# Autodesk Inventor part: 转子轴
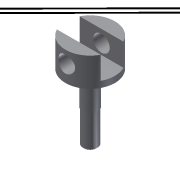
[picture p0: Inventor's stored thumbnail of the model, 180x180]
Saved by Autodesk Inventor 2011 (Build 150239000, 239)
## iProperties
Created: 2012-10
Part Number: 转子轴
Document SubType Name: Modeling
Designer: Administrator
Density: 1 g/cm^3
Author: Administrator
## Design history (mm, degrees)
sketch "草图1"
  geometry: C1 r 24 at (0, 0); 1 further point
  constraints: 1 centre point, 1 coincident
  dimensions: "d0" = 48 diameter of C1
extrude "拉伸1" new body sketch "草图1" distance "d1" = 28; taper "d2" = 0 deg
node "工作平面1"
sketch "草图2"
  geometry: L1 (11, 28)-(-11, 28); L2 (-11, 28)-(-11, 6); L3 (-11, 6)-(11, 6); L4 (11, 6)-(11, 28); L5 (-24, 28)-(24, 28) reference; L6 (-24, 0)-(24, 0) reference; 2 further points
  constraints: 8 end point, 2 midpoint, 2 parallel, 1 horizontal, 1 perpendicular
  dimensions: "d3" = 22 distance of L3.end L1.start; "d4" = 22 distance of L1.start L1.end
extrude "拉伸2" cut sketch "草图2" stored distance "d5" = 0; taper "d6" = 0 deg
node "工作平面2"
sketch "草图3"
  geometry: L1 (-21.331, 28)-(21.331, 28) reference; C1 r 8 at (0, 16); 1 further point
  constraints: 1 centre point
  dimensions: "d8" = 16 diameter of C1; "d9" = 12 distance from line of L1 C1.centre
extrude "拉伸3" cut sketch "草图3" stored distance "d10" = 0; taper "d11" = 0 deg
sketch "草图5"
  geometry: L1 (0, 0)-(0, -87.257); L2 (-7.5, 0)-(-7.5, -32); L3 (-7.5, -32)-(-7, -32); L4 (-7, -32)-(-7, -63); L5 (-6, -64)-(0, -64); L6 (-24, 0)-(24, 0) reference; L7 (-7, -63)-(-6, -64); L8 (-7.5, 0)-(0, 0); 2 further points
  constraints: 14 end point, 4 point on line, 2 parallel, 2 perpendicular, 1 collinear, 1 midpoint, 1 vertical
  dimensions: "d12" = 32 distance of L2.start L2.end; "d13" = 32 distance of L3.end point (-7, -64); "d16" = 7 distance of point (-7, -64) L5.end; "d17" = 7.5 distance between parallel lines of L2 L1; "d18" = 1 distance of L4.end point (-7, -64); "d19" = 1 distance of L5.start point (-7, -64) (= d18)
revolve "旋转1" sketch "草图5" stored, may be unused: angle "d20" = 90 deg
sketch "草图6"
  geometry: L1 (7.5, -32)-(7.5, 0) reference; L2 (-24, 0)-(24, 0) reference; L3 (7.5, -2)-(7, -1.5); L4 (7, -1.5)-(7, 0); L5 (7.5, 0.5)-(9, 0.5); L6 (9, 0.5)-(9.5, 0); L7 (0, 0)-(0, -30.045); A1 r 0.5 centre (7.5, 0) between (7.5, 0.5) and (7, 0)
  constraints: 10 end point, 3 perpendicular, 2 point on circle, 2 point on line, 2 tangent, 1 centre point, 1 parallel
  dimensions: "d21" = 45 deg angle of L1 L3; "d22" = 0.5 distance between parallel lines of L4 L1; "d23" = 0.5 distance between parallel lines of L2 L5; "d24" = 2 distance from line of L3.start L2; "d25" = 2 distance from line of L6.end L1; "d26" = 0.5 radius of A1
revolve "旋转2" sketch "草图6" stored, may be unused: angle "d27" = 90 deg
node "实体1"
node "投影回路1"
other parameters: "d7" = -25.5
